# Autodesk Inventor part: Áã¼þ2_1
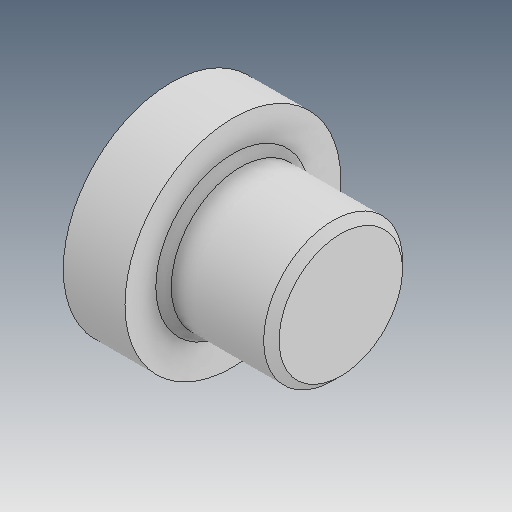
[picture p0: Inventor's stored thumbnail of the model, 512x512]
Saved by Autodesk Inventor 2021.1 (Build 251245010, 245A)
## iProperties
Created: 2019-04
Part Number: Áã¼þ2_1
Material: Ogólny
Document SubType Name: Modeling
Designer: user
Density: 1 g/cm^3
Appearance: Domyślna
Author: user
Revision Number: ÈÎºÎ
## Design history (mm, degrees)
feature "ÊäÈë1"
node "Bryła1"
